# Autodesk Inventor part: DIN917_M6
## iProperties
Created: 2007-03
Part Number: DIN917_M6
Document SubType Name: Modeling
Designer: Andy Moles
Material: Steel
Mass: 4.20266 g
Surface Area: 5.20458 cm^2
Volume: 0.53537 cm^3
Density: 7.85 g/cm^3
Author: Andy Moles
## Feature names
1. Base1
